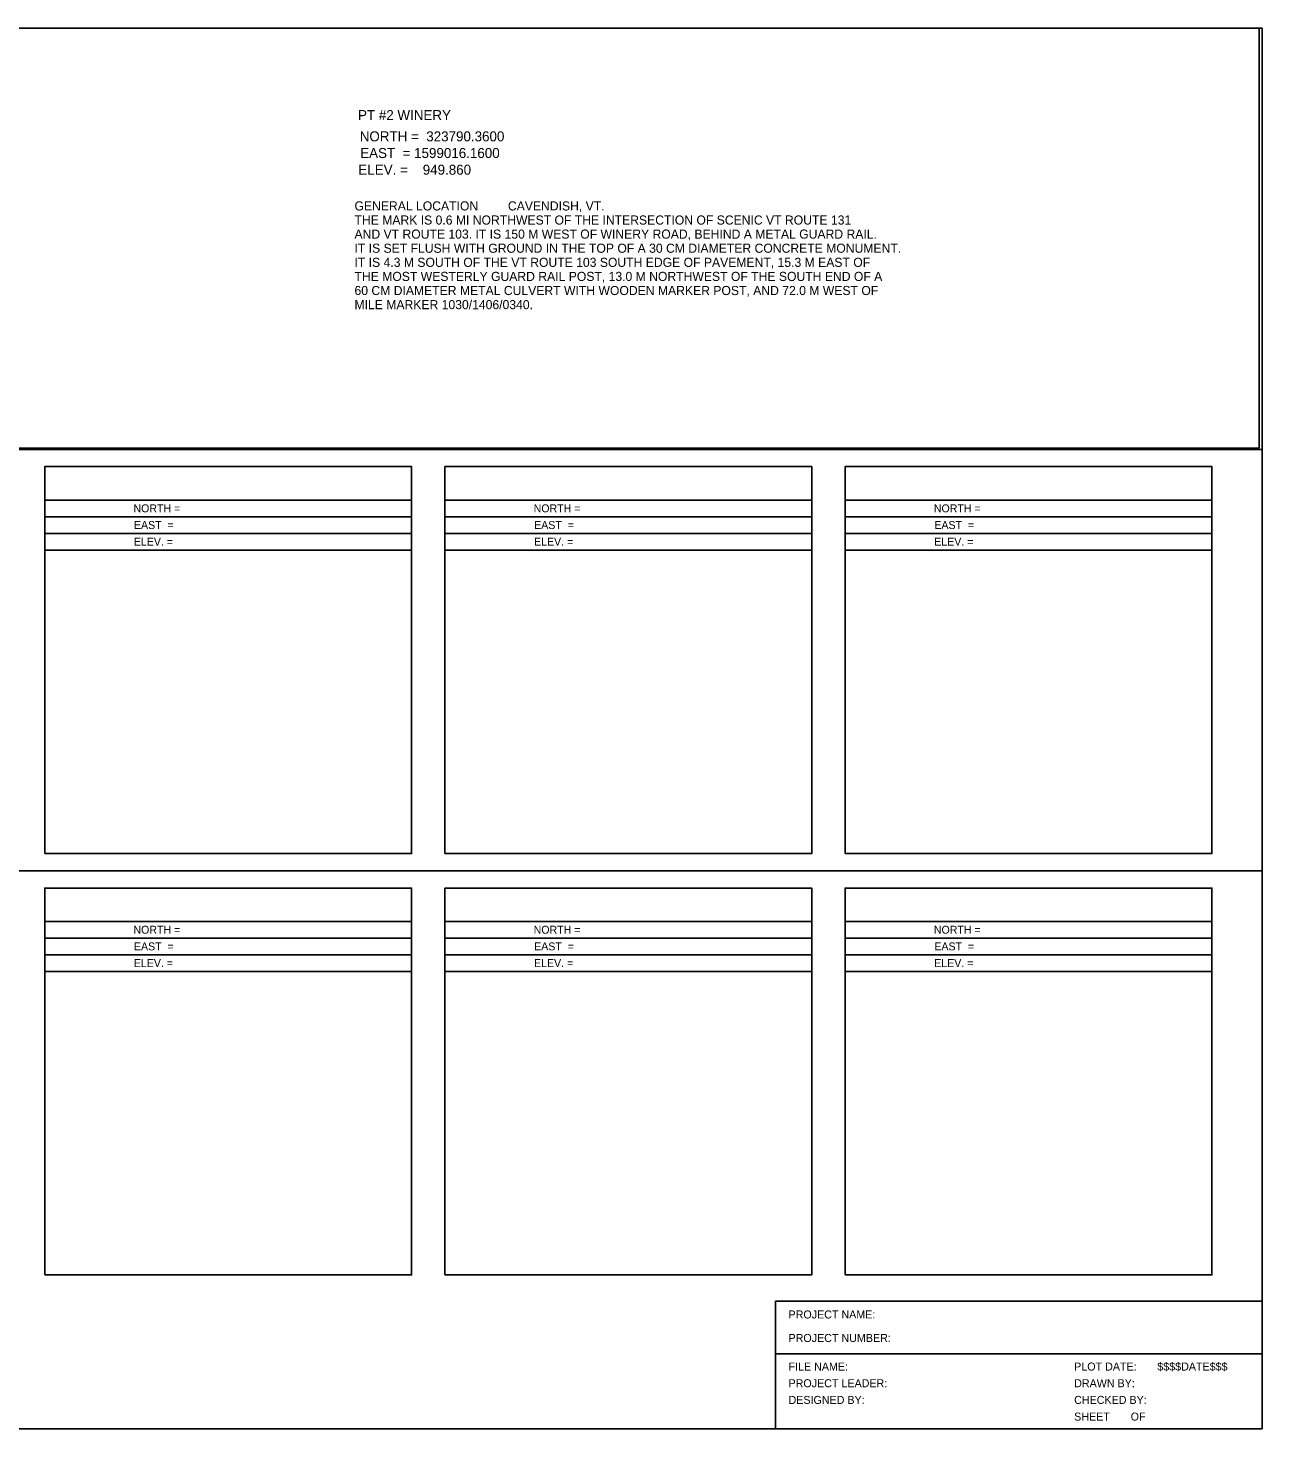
# Model space of a CAD drawing. Extents: x 1603676 to 1604316, y 320315 to 320735.
# Drawn here: x 1603945.9 to 1604315.9, y 320314.6 to 320734.6 of the extents above; entities that cross this region are included whole.
import ezdxf

# ---------------------------------------------------------------- set-up
doc = ezdxf.new("R2010")
doc.units = 0
for name, color, linetype in [('LDEFAULT', 7, 'Continuous'), ('NBL1', 7, 'Continuous'), ('NBL2', 7, 'Continuous')]:
    doc.layers.add(name, color=color, linetype=linetype)

msp = doc.modelspace()

# ---------------------------------------------------------------- linework, layer by layer
at = {"layer": 'NBL1'}
for p, q in [((1603697.37, 320734.48), (1604315.12, 320734.48)), ((1604315.12, 320734.48), (1604315.12, 320608.58)), ((1603675.93, 320608.23), (1604315.93, 320608.23)), ((1604315.12, 320608.58), (1603697.37, 320608.58)), ((1604060.92, 320593.07), (1603950.92, 320593.07)), ((1604180.92, 320593.07), (1604070.92, 320593.07)), ((1604300.92, 320593.07), (1604190.92, 320593.07)), ((1604060.92, 320588.07), (1603950.92, 320588.07)), ((1604180.92, 320588.07), (1604070.92, 320588.07)), ((1604300.92, 320588.07), (1604190.92, 320588.07)), ((1604060.92, 320583.07), (1603950.92, 320583.07)), ((1604180.92, 320583.07), (1604070.92, 320583.07)), ((1604300.92, 320583.07), (1604190.92, 320583.07)), ((1604060.92, 320578.07), (1603950.92, 320578.07)), ((1604180.92, 320578.07), (1604070.92, 320578.07)), ((1604300.92, 320578.07), (1604190.92, 320578.07)), ((1603675.93, 320481.9), (1604315.93, 320481.9)), ((1604060.92, 320466.73), (1603950.92, 320466.73)), ((1604180.92, 320466.73), (1604070.92, 320466.73)), ((1604300.92, 320466.73), (1604190.92, 320466.73)), ((1604060.92, 320461.73), (1603950.92, 320461.73)), ((1604180.92, 320461.73), (1604070.92, 320461.73)), ((1604300.92, 320461.73), (1604190.92, 320461.73)), ((1604060.92, 320456.73), (1603950.92, 320456.73)), ((1604180.92, 320456.73), (1604070.92, 320456.73)), ((1604300.92, 320456.73), (1604190.92, 320456.73)), ((1604060.92, 320451.73), (1603950.92, 320451.73)), ((1604180.92, 320451.73), (1604070.92, 320451.73)), ((1604300.92, 320451.73), (1604190.92, 320451.73)), ((1604170.09, 320352.9), (1604315.93, 320352.9)), ((1604170.09, 320314.57), (1604170.09, 320352.9)), ((1604170.09, 320337.07), (1604315.93, 320337.07))]:
    msp.add_line(p, q, dxfattribs=at)
for points in [[(1604315.93, 320314.57), (1603675.93, 320314.57), (1603675.93, 320734.57), (1604315.93, 320734.57)], [(1603950.92, 320487.07), (1604060.92, 320487.07), (1604060.92, 320603.07), (1603950.92, 320603.07)], [(1604070.92, 320487.07), (1604180.92, 320487.07), (1604180.92, 320603.07), (1604070.92, 320603.07)], [(1604190.92, 320487.07), (1604300.92, 320487.07), (1604300.92, 320603.07), (1604190.92, 320603.07)], [(1603950.92, 320360.73), (1604060.92, 320360.73), (1604060.92, 320476.73), (1603950.92, 320476.73)], [(1604070.92, 320360.73), (1604180.92, 320360.73), (1604180.92, 320476.73), (1604070.92, 320476.73)], [(1604190.92, 320360.73), (1604300.92, 320360.73), (1604300.92, 320476.73), (1604190.92, 320476.73)]]:
    msp.add_lwpolyline(points, close=True, dxfattribs=at)

# ---------------------------------------------------------------- texts
at = {"layer": 'LDEFAULT'}
for s, p in [('GENERAL LOCATION ', (1604043.82, 320679.87)), ('CAVENDISH, VT.', (1604089.82, 320679.87)), ('THE MARK IS 0.6 MI NORTHWEST OF THE INTERSECTION OF SCENIC VT ROUTE 131 ', (1604043.82, 320675.64)), ('AND VT ROUTE 103. IT IS 150 M WEST OF WINERY ROAD, BEHIND A METAL GUARD RAIL. ', (1604043.82, 320671.42)), ('IT IS SET FLUSH WITH GROUND IN THE TOP OF A 30 CM DIAMETER CONCRETE MONUMENT. ', (1604043.82, 320667.19)), ('IT IS 4.3 M SOUTH OF THE VT ROUTE 103 SOUTH EDGE OF PAVEMENT, 15.3 M EAST OF ', (1604043.82, 320662.96)), ('THE MOST WESTERLY GUARD RAIL POST, 13.0 M NORTHWEST OF THE SOUTH END OF A ', (1604043.82, 320658.74)), ('60 CM DIAMETER METAL CULVERT WITH WOODEN MARKER POST, AND 72.0 M WEST OF ', (1604043.82, 320654.51)), ('MILE MARKER 1030/1406/0340.', (1604043.82, 320650.28))]:
    msp.add_text(s, height=2.7273, dxfattribs=at).set_placement(p)
at = {"layer": 'NBL1'}
for s, height, p in [('NORTH =             ', 2.375, (1603977.54, 320589.38)), ('NORTH =             ', 2.375, (1604097.54, 320589.38)), ('NORTH =             ', 2.375, (1604217.54, 320589.38)), ('EAST  =             ', 2.375, (1603977.69, 320584.38)), ('EAST  =             ', 2.375, (1604097.69, 320584.38)), ('EAST  =             ', 2.375, (1604217.69, 320584.38)), ('ELEV. =             ', 2.375, (1603977.65, 320579.38)), ('ELEV. =             ', 2.375, (1604097.65, 320579.38)), ('ELEV. =             ', 2.375, (1604217.65, 320579.38)), ('NORTH =             ', 2.375, (1603977.54, 320463.05)), ('NORTH =             ', 2.375, (1604097.54, 320463.05)), ('NORTH =             ', 2.375, (1604217.54, 320463.05)), ('EAST  =             ', 2.375, (1603977.69, 320458.05)), ('EAST  =             ', 2.375, (1604097.69, 320458.05)), ('EAST  =             ', 2.375, (1604217.69, 320458.05)), ('ELEV. =             ', 2.375, (1603977.65, 320453.05)), ('ELEV. =             ', 2.375, (1604097.65, 320453.05)), ('ELEV. =             ', 2.375, (1604217.65, 320453.05)), ('PROJECT NAME:', 2.4, (1604173.96, 320347.7)), ('PROJECT NUMBER:', 2.4, (1604173.96, 320340.65)), ('FILE NAME:', 2.4, (1604173.96, 320332.08)), ('PLOT DATE:', 2.4, (1604259.61, 320332.08)), ('$$$$DATE$$$', 2.4, (1604284.54, 320332.08)), ('PROJECT LEADER:', 2.4, (1604173.96, 320327.08)), ('DRAWN BY:', 2.4, (1604259.61, 320327.08)), ('DESIGNED BY:', 2.4, (1604173.96, 320322.08)), ('CHECKED BY:', 2.4, (1604259.61, 320322.08)), ('SHEET       OF', 2.4, (1604259.61, 320317.08))]:
    msp.add_text(s, height=height, dxfattribs=at).set_placement(p)
at = {"layer": 'NBL2'}
for s, p in [('PT #2 WINERY        ', (1604044.88, 320706.97)), ('NORTH =  323790.3600', (1604045.39, 320700.59)), ('EAST  = 1599016.1600', (1604045.53, 320695.59)), ('ELEV. =    949.860  ', (1604044.99, 320690.59))]:
    msp.add_text(s, height=3, dxfattribs=at).set_placement(p)

doc.saveas('drawing.dxf')
